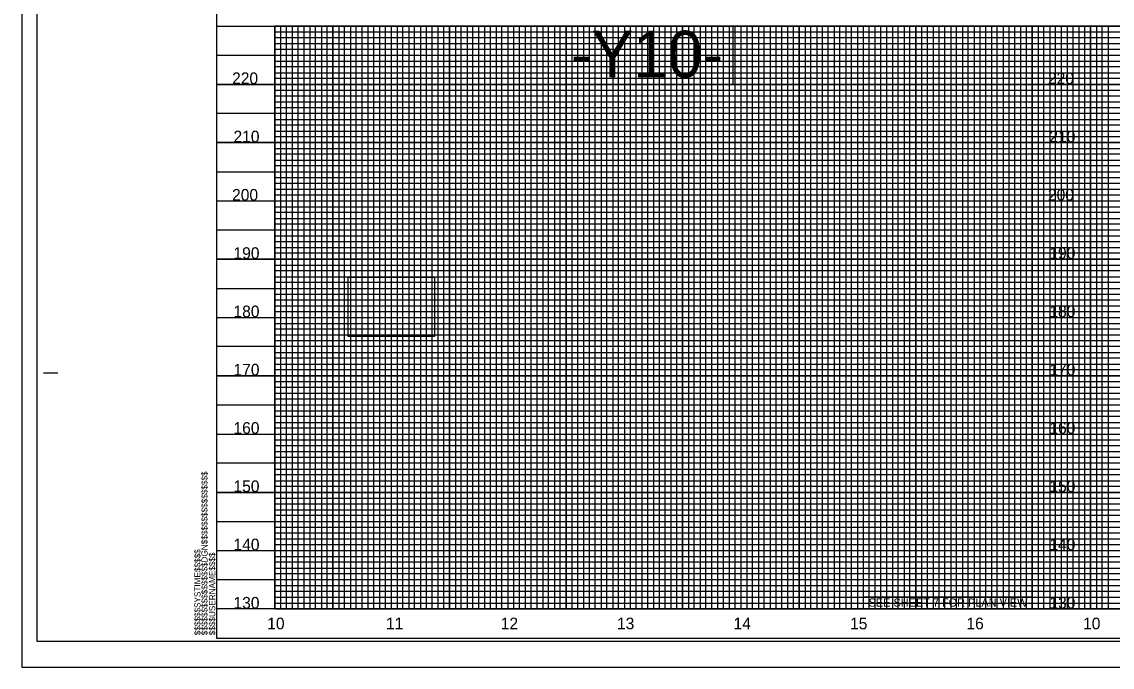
# Model space of a CAD drawing. Extents: x 1779926 to 1781626, y 618464 to 619564.
# Drawn here: x 1779926 to 1780862, y 618464 to 619018 of the extents above; entities that cross this region are included whole.
import ezdxf

# ---------------------------------------------------------------- set-up
doc = ezdxf.new("R2010")
doc.units = 0
for name, color, linetype in [('Exist Vertical Profile Horizontal Axis Label Major', 7, 'Continuous'), ('Exist Vertical Profile Vertical Axis Label', 7, 'Continuous'), ('Prop DSN Text', 7, 'Continuous'), ('Prop Grid Mask', 7, 'Continuous'), ('Sheet DOT Grid CELL', 7, 'Continuous'), ('Sheet Layout Profile Border Port 2', 7, 'Continuous'), ('Sheet Plot Border Inside CELL', 7, 'Continuous'), ('Sheet Plot Border Outside CELL', 7, 'Continuous'), ('Sheet Profile CELL', 7, 'Continuous'), ('Sheet Profile Grid Major CELL', 7, 'Continuous'), ('Sheet Profile Grid Middle CELL', 7, 'Continuous'), ('Sheet Profile Grid Minor CELL', 7, 'Continuous')]:
    doc.layers.add(name, color=color, linetype=linetype)

msp = doc.modelspace()

# ---------------------------------------------------------------- linework, layer by layer
at = {"layer": 'Prop Grid Mask'}
for points in [[(1780536.2, 619014.19), (1780392.96, 619014.19), (1780392.96, 618964.19), (1780536.2, 618964.19)], [(1780792.96, 619014.19), (1780842.96, 619014.19), (1780842.96, 618514.19), (1780792.96, 618514.19)], [(1780205.9, 618798.75), (1780280.15, 618798.75), (1780280.15, 618747.85), (1780205.9, 618747.85)], [(1780792.96, 618524.19), (1780647.96, 618524.19), (1780647.96, 618514.19), (1780792.96, 618514.19)]]:
    msp.add_lwpolyline(points, close=True, dxfattribs=at)
at = {"layer": 'Sheet DOT Grid CELL'}
for p, q in [((1780092.96, 619014.19), (1781592.85, 619014.19)), ((1780142.96, 619014.19), (1780142.96, 618514.19)), ((1780192.96, 619014.19), (1780192.96, 618514.19)), ((1780242.96, 619014.19), (1780242.96, 618514.19)), ((1780292.96, 619014.19), (1780292.96, 618514.19)), ((1780342.96, 619014.19), (1780342.96, 618514.19)), ((1780392.96, 619014.19), (1780392.96, 618514.19)), ((1780442.96, 619014.19), (1780442.96, 618514.19)), ((1780492.96, 619014.19), (1780492.96, 618514.19)), ((1780542.96, 619014.19), (1780542.96, 618514.19)), ((1780592.96, 619014.19), (1780592.96, 618514.19)), ((1780642.96, 619014.19), (1780642.96, 618514.19)), ((1780692.96, 619014.19), (1780692.96, 618514.19)), ((1780742.96, 619014.19), (1780742.96, 618514.19)), ((1780792.96, 619014.19), (1780792.96, 618514.19)), ((1780792.96, 618514.19), (1780792.96, 619014.19)), ((1780842.96, 619014.19), (1780842.96, 618514.19)), ((1780842.96, 618514.19), (1780842.96, 619014.19)), ((1780092.96, 618964.19), (1781592.85, 618964.19)), ((1780092.96, 618914.19), (1781592.85, 618914.19)), ((1780092.96, 618864.19), (1781592.85, 618864.19)), ((1780092.96, 618814.19), (1781592.85, 618814.19)), ((1780092.96, 618764.19), (1781592.85, 618764.19)), ((1780092.96, 618714.19), (1781592.85, 618714.19)), ((1780092.96, 618664.19), (1781592.85, 618664.19)), ((1780092.96, 618614.19), (1781592.85, 618614.19)), ((1780092.96, 618564.19), (1781592.85, 618564.19))]:
    msp.add_line(p, q, dxfattribs=at)
at = {"layer": 'Sheet Layout Profile Border Port 2'}
msp.add_lwpolyline([(1780142.96, 619014.19), (1781542.96, 619014.19), (1781542.96, 618514.19), (1780142.96, 618514.19)], close=True, dxfattribs=at)
msp.add_lwpolyline([(1781442.96, 619014.19), (1780142.96, 619014.19), (1780142.96, 618514.19), (1781542.96, 618514.19), (1781542.96, 619014.19)], dxfattribs=at)
at = {"layer": 'Sheet Plot Border Inside CELL'}
msp.add_lwpolyline([(1779938.96, 618486.64), (1781605.46, 618486.64), (1781605.46, 619541.74), (1779938.96, 619541.74)], close=True, dxfattribs=at)
at = {"layer": 'Sheet Plot Border Outside CELL'}
msp.add_lwpolyline([(1779925.96, 618464.19), (1781625.96, 618464.19), (1781625.96, 619564.19), (1779925.96, 619564.19)], close=True, dxfattribs=at)
at = {"layer": 'Sheet Profile CELL'}
for p, q in [((1780092.96, 619014.19), (1781592.96, 619014.19)), ((1779944.46, 618716.69), (1779956.96, 618716.69)), ((1781592.96, 618514.19), (1780092.96, 618514.19)), ((1780092.96, 618489.19), (1781592.96, 618489.19)), ((1780092.96, 618489.19), (1780092.96, 618489.19)), ((1780092.96, 618489.19), (1780092.96, 618489.19)), ((1780092.96, 618489.19), (1780092.96, 618489.19)), ((1780092.96, 618489.19), (1780092.96, 618489.19)), ((1780092.96, 618489.19), (1780092.96, 618489.19)), ((1780092.96, 618489.19), (1780092.96, 618489.19)), ((1780092.96, 618489.19), (1780092.96, 618489.19))]:
    msp.add_line(p, q, dxfattribs=at)
msp.add_lwpolyline([(1781592.96, 619539.19), (1780092.96, 619539.19), (1780092.96, 618489.19), (1781592.96, 618489.19)], close=True, dxfattribs=at)
msp.add_lwpolyline([(1780130.46, 618489.19), (1780130.46, 618489.19)], dxfattribs=at)
at = {"layer": 'Sheet Profile Grid Major CELL'}
for p, q in [((1780592.96, 619014.19), (1780642.96, 619014.19)), ((1780692.96, 619014.19), (1780742.96, 619014.19)), ((1780792.96, 619014.19), (1780842.96, 619014.19)), ((1780092.96, 618514.19), (1780092.96, 618514.19))]:
    msp.add_line(p, q, dxfattribs=at)
for points in [[(1780142.96, 619014.19), (1780142.96, 618514.19), (1780192.96, 618514.19), (1780192.96, 619014.19), (1780242.96, 619014.19), (1780242.96, 618514.19), (1780292.96, 618514.19), (1780292.96, 619014.19), (1780342.96, 619014.19), (1780342.96, 618514.19), (1780392.96, 618514.19), (1780392.96, 619014.19), (1780442.96, 619014.19), (1780442.96, 618514.19), (1780492.96, 618514.19), (1780492.96, 619014.19), (1780542.96, 619014.19), (1780542.96, 618514.19), (1780592.96, 618514.19), (1780592.96, 619014.19), (1780642.96, 619014.19), (1780642.96, 618514.19), (1780692.96, 618514.19), (1780692.96, 619014.19), (1780742.96, 619014.19), (1780742.96, 618514.19), (1780792.96, 618514.19), (1780792.96, 619014.19), (1780842.96, 619014.19), (1780842.96, 618514.19), (1780892.96, 618514.19)], [(1781592.96, 618964.19), (1780092.96, 618964.19)], [(1781592.96, 618914.19), (1780092.96, 618914.19), (1780092.96, 618864.19), (1781592.96, 618864.19)], [(1781592.96, 618814.19), (1780092.96, 618814.19), (1780092.96, 618764.19), (1781592.96, 618764.19)], [(1781592.96, 618714.19), (1780092.96, 618714.19), (1780092.96, 618664.19), (1781592.96, 618664.19)], [(1781592.96, 618614.19), (1780092.96, 618614.19), (1780092.96, 618614.19), (1780092.96, 618564.19), (1781592.96, 618564.19)], [(1781592.96, 618514.19), (1780092.96, 618514.19)]]:
    msp.add_lwpolyline(points, dxfattribs=at)
at = {"layer": 'Sheet Profile Grid Middle CELL'}
for points in [[(1780117.96, 619014.19), (1780167.96, 619014.19), (1780167.96, 618514.19), (1780217.96, 618514.19), (1780217.96, 619014.19), (1780267.96, 619014.19), (1780267.96, 618514.19), (1780317.96, 618514.19), (1780317.96, 619014.19), (1780367.96, 619014.19), (1780367.96, 618514.19), (1780417.96, 618514.19), (1780417.96, 619014.19), (1780467.96, 619014.19), (1780467.96, 618514.19), (1780517.96, 618514.19), (1780517.96, 619014.19), (1780567.96, 619014.19), (1780567.96, 618514.19), (1780617.96, 618514.19), (1780617.96, 619014.19), (1780667.96, 619014.19), (1780667.96, 618514.19), (1780717.96, 618514.19), (1780717.96, 618514.19), (1780717.96, 619014.19), (1780767.96, 619014.19), (1780767.96, 618514.19), (1780817.96, 618514.19), (1780817.96, 619014.19), (1780867.96, 619014.19)], [(1780092.96, 618989.19), (1781592.96, 618989.19)], [(1781592.96, 618939.19), (1780092.96, 618939.19), (1780092.96, 618889.19), (1781592.96, 618889.19)], [(1781592.96, 618839.19), (1780092.96, 618839.19), (1780092.96, 618789.19), (1781592.96, 618789.19)], [(1781592.96, 618739.19), (1780092.96, 618739.19), (1780092.96, 618689.19), (1781592.96, 618689.19)], [(1781592.96, 618639.19), (1780092.96, 618639.19), (1780092.96, 618589.19), (1781592.96, 618589.19)], [(1781592.96, 618539.19), (1780092.96, 618539.19)]]:
    msp.add_lwpolyline(points, dxfattribs=at)
at = {"layer": 'Sheet Profile Grid Minor CELL'}
for p, q in [((1780142.96, 619009.19), (1781542.96, 619009.19)), ((1781542.96, 619004.19), (1780142.96, 619004.19)), ((1780142.96, 618999.19), (1781542.96, 618999.19)), ((1781542.96, 618994.19), (1780142.96, 618994.19)), ((1780142.96, 618984.19), (1781542.96, 618984.19)), ((1781542.96, 618979.19), (1780142.96, 618979.19)), ((1780142.96, 618974.19), (1781542.96, 618974.19)), ((1781542.96, 618969.19), (1780142.96, 618969.19)), ((1780142.96, 618959.19), (1781542.96, 618959.19)), ((1781542.96, 618954.19), (1780142.96, 618954.19)), ((1780142.96, 618949.19), (1781542.96, 618949.19)), ((1781542.96, 618944.19), (1780142.96, 618944.19)), ((1780142.96, 618934.19), (1781542.96, 618934.19)), ((1781542.96, 618929.19), (1780142.96, 618929.19)), ((1780142.96, 618924.19), (1781542.96, 618924.19)), ((1781542.96, 618919.19), (1780142.96, 618919.19)), ((1780142.96, 618909.19), (1781542.96, 618909.19)), ((1781542.96, 618904.19), (1780142.96, 618904.19)), ((1780142.96, 618899.19), (1781542.96, 618899.19)), ((1781542.96, 618894.19), (1780142.96, 618894.19)), ((1780142.96, 618884.19), (1781542.96, 618884.19)), ((1781542.96, 618879.19), (1780142.96, 618879.19)), ((1780142.96, 618874.19), (1781542.96, 618874.19)), ((1781542.96, 618869.19), (1780142.96, 618869.19)), ((1780142.96, 618859.19), (1781542.96, 618859.19)), ((1781542.96, 618854.19), (1780142.96, 618854.19)), ((1780142.96, 618849.19), (1781542.96, 618849.19)), ((1781542.96, 618844.19), (1780142.96, 618844.19)), ((1780142.96, 618834.19), (1781542.96, 618834.19)), ((1781542.96, 618829.19), (1780142.96, 618829.19)), ((1780142.96, 618824.19), (1781542.96, 618824.19)), ((1781542.96, 618819.19), (1780142.96, 618819.34)), ((1780142.96, 618809.19), (1781542.96, 618809.19)), ((1781542.96, 618804.19), (1780142.96, 618804.19)), ((1780142.96, 618799.19), (1781542.96, 618799.19)), ((1781542.96, 618794.19), (1780142.96, 618794.19)), ((1780142.96, 618784.19), (1781542.96, 618784.19)), ((1781542.96, 618779.19), (1780142.96, 618779.19)), ((1780142.96, 618774.19), (1781542.96, 618774.19)), ((1781542.96, 618769.19), (1780142.96, 618769.19)), ((1780142.96, 618759.19), (1781542.96, 618759.19)), ((1781542.96, 618754.19), (1780142.96, 618754.19)), ((1780142.96, 618749.19), (1781542.96, 618749.19)), ((1781542.96, 618744.19), (1780142.96, 618744.19)), ((1780142.96, 618734.19), (1781542.96, 618734.19)), ((1781542.96, 618729.19), (1780142.96, 618729.19)), ((1780142.96, 618724.19), (1781542.96, 618724.19)), ((1781542.96, 618719.19), (1780142.96, 618719.19)), ((1780142.96, 618709.19), (1781542.96, 618709.19)), ((1781542.96, 618704.19), (1780142.96, 618704.19)), ((1780142.96, 618699.19), (1781542.96, 618699.19)), ((1781542.96, 618694.19), (1780142.96, 618694.19)), ((1780142.96, 618684.19), (1781542.96, 618684.19)), ((1781542.96, 618679.19), (1780142.96, 618679.19)), ((1780142.96, 618674.19), (1781542.96, 618674.19)), ((1781542.96, 618669.19), (1780142.96, 618669.19)), ((1780142.96, 618659.19), (1781542.96, 618659.19)), ((1781542.96, 618654.19), (1780142.96, 618654.19)), ((1780142.96, 618649.19), (1781542.96, 618649.19)), ((1781542.96, 618644.19), (1780142.96, 618644.19)), ((1780142.96, 618634.19), (1781542.96, 618634.19)), ((1781542.96, 618629.19), (1780142.96, 618629.19)), ((1780142.96, 618624.19), (1781542.96, 618624.19)), ((1781542.96, 618619.19), (1780142.96, 618619.19)), ((1780142.96, 618609.19), (1781542.96, 618609.19)), ((1781542.96, 618604.19), (1780142.96, 618604.19)), ((1780142.96, 618599.19), (1781542.96, 618599.19)), ((1781542.96, 618594.19), (1780142.96, 618594.19)), ((1780142.96, 618584.19), (1781542.96, 618584.19)), ((1781542.96, 618579.19), (1780142.96, 618579.19)), ((1780142.96, 618574.19), (1781542.96, 618574.19)), ((1781542.96, 618569.19), (1780142.96, 618569.19)), ((1780142.96, 618559.19), (1781542.96, 618559.19)), ((1781542.96, 618554.19), (1780142.96, 618554.19)), ((1780142.96, 618549.19), (1781542.96, 618549.19)), ((1781542.96, 618544.19), (1780142.96, 618544.19)), ((1780142.96, 618534.19), (1781542.96, 618534.19)), ((1781542.96, 618529.19), (1780142.96, 618529.19)), ((1780142.96, 618524.19), (1781542.96, 618524.19)), ((1780142.96, 618519.19), (1781542.96, 618519.19))]:
    msp.add_line(p, q, dxfattribs=at)
for points in [[(1780142.96, 619014.19), (1780147.96, 619014.19), (1780147.96, 618514.19), (1780152.96, 618514.19), (1780152.96, 619014.19), (1780157.96, 619014.19), (1780157.96, 618514.19), (1780162.96, 618514.19), (1780162.96, 619014.19), (1780172.96, 619014.19), (1780172.96, 618514.19), (1780177.96, 618514.19), (1780177.96, 619014.19), (1780182.96, 619014.19), (1780182.96, 618514.19), (1780187.96, 618514.19), (1780197.96, 618514.19), (1780202.96, 618514.19), (1780202.96, 619014.19), (1780207.96, 619014.19), (1780207.96, 618514.19), (1780212.96, 618514.19), (1780212.96, 619014.19), (1780222.96, 619014.19), (1780222.96, 618514.19), (1780227.96, 618514.19), (1780227.96, 619014.19), (1780232.96, 619014.19), (1780232.96, 618514.19), (1780237.96, 618514.19), (1780237.96, 619014.19), (1780247.96, 619014.19), (1780247.96, 618514.19), (1780252.96, 618514.19), (1780252.96, 619014.19), (1780257.96, 619014.19), (1780257.96, 618514.19), (1780262.96, 618514.19), (1780262.96, 619014.19), (1780272.96, 619014.19), (1780272.96, 618514.19), (1780277.96, 618514.19), (1780277.96, 619014.19), (1780282.96, 619014.19), (1780282.96, 618514.19), (1780287.96, 618514.19), (1780287.96, 619014.19), (1780297.96, 619014.19), (1780297.96, 618514.19), (1780302.96, 618514.19), (1780302.96, 619014.19), (1780307.96, 619014.19), (1780307.96, 618514.19), (1780312.96, 618514.19), (1780312.96, 619014.19), (1780322.96, 619014.19), (1780322.96, 618514.19), (1780327.96, 618514.19), (1780327.96, 619014.19), (1780332.96, 619014.19), (1780332.96, 618514.19), (1780337.96, 618514.19), (1780337.96, 619014.19), (1780347.96, 619014.19), (1780347.96, 618514.19), (1780352.96, 618514.19), (1780352.96, 619014.19), (1780357.96, 619014.19), (1780357.96, 618514.19)], [(1780187.96, 618514.19), (1780187.96, 619014.19), (1780197.96, 619014.19), (1780197.96, 618514.19)], [(1780357.96, 618514.19), (1780362.96, 618514.19), (1780362.96, 619014.19), (1780372.96, 619014.19), (1780372.96, 618514.19), (1780377.96, 618514.19), (1780377.96, 619014.19), (1780382.96, 619014.19), (1780382.96, 618514.19), (1780387.96, 618514.19), (1780387.96, 619014.19), (1780397.96, 619014.19), (1780397.96, 618514.19), (1780402.96, 618514.19), (1780402.96, 619014.19), (1780407.96, 619014.19), (1780407.96, 618514.19), (1780412.96, 618514.19), (1780412.96, 619014.19), (1780422.96, 619014.19), (1780422.96, 618514.19), (1780427.96, 618514.19), (1780427.96, 619014.19), (1780432.96, 619014.19), (1780432.96, 618514.19), (1780437.96, 618514.19), (1780437.96, 619014.19), (1780447.96, 619014.19), (1780447.96, 618514.19), (1780452.96, 618514.19), (1780452.96, 619014.19), (1780457.96, 619014.19), (1780457.96, 618514.19), (1780462.96, 618514.19), (1780462.96, 619014.19), (1780472.96, 619014.19), (1780472.96, 618514.19), (1780477.96, 618514.19), (1780477.96, 619014.19), (1780482.96, 619014.19), (1780482.96, 618514.19), (1780487.96, 618514.19), (1780487.96, 619014.19), (1780497.96, 619014.19), (1780497.96, 618514.19), (1780502.96, 618514.19), (1780502.96, 619014.19), (1780507.96, 619014.19), (1780507.96, 618514.19), (1780512.96, 618514.19), (1780512.96, 619014.19), (1780522.96, 619014.19), (1780522.96, 618514.19), (1780527.96, 618514.19), (1780527.96, 619014.19), (1780532.96, 619014.19), (1780532.96, 618514.19), (1780537.96, 618514.19), (1780537.96, 619014.19), (1780547.96, 619014.19), (1780547.96, 618514.19), (1780552.96, 618514.19), (1780552.96, 619014.19), (1780557.96, 619014.19), (1780557.96, 618514.19), (1780562.96, 618514.19), (1780562.96, 619014.19), (1780572.96, 619014.19), (1780572.96, 618514.19), (1780577.96, 618514.19), (1780577.96, 619014.19), (1780582.96, 619014.19), (1780582.96, 618514.19), (1780587.96, 618514.19), (1780587.96, 619014.19), (1780597.96, 619014.19), (1780597.96, 618514.19), (1780602.96, 618514.19), (1780602.96, 619014.19), (1780607.96, 619014.19), (1780607.96, 618514.19), (1780612.96, 618514.19), (1780612.96, 619014.19), (1780622.96, 619014.19), (1780622.96, 618514.19), (1780627.96, 618514.19), (1780627.96, 619014.19), (1780632.96, 619014.19), (1780632.96, 618514.19), (1780637.96, 618514.19), (1780637.96, 619014.19), (1780647.96, 619014.19), (1780647.96, 618514.19), (1780652.96, 618514.19), (1780652.96, 619014.19), (1780657.96, 619014.19), (1780657.96, 618514.19), (1780662.96, 618514.19), (1780662.96, 619014.19), (1780672.96, 619014.19)], [(1780672.96, 619014.19), (1780672.96, 618514.19), (1780677.96, 618514.19), (1780677.96, 619014.19), (1780682.96, 619014.19), (1780682.96, 618514.19), (1780687.96, 618514.19), (1780687.96, 619014.19), (1780697.96, 619014.19), (1780697.96, 618514.19), (1780702.96, 618514.19), (1780702.96, 619014.19), (1780707.96, 619014.19), (1780707.96, 618514.19), (1780712.96, 618514.19), (1780712.96, 619014.19), (1780722.96, 619014.19), (1780722.96, 618514.19), (1780727.96, 618514.19), (1780727.96, 619014.19), (1780732.96, 619014.19), (1780732.96, 618514.19), (1780737.96, 618514.19), (1780737.96, 619014.19), (1780747.96, 619014.19), (1780747.96, 618514.19), (1780752.96, 618514.19), (1780752.96, 619014.19), (1780757.96, 619014.19), (1780757.96, 618514.19), (1780762.96, 618514.19), (1780762.96, 619014.19), (1780772.96, 619014.19), (1780772.96, 618514.19), (1780777.96, 618514.19), (1780777.96, 619014.19), (1780782.96, 619014.19), (1780782.96, 618514.19), (1780787.96, 618514.19), (1780787.96, 619014.19), (1780797.96, 619014.19), (1780797.96, 618514.19), (1780797.96, 618514.19), (1780802.96, 618514.19), (1780802.96, 619014.19), (1780807.96, 619014.19), (1780807.96, 618514.19), (1780812.96, 618514.19), (1780812.96, 619014.19), (1780822.96, 619014.19), (1780822.96, 618514.19), (1780827.96, 618514.19), (1780827.96, 619014.19), (1780832.96, 619014.19), (1780832.96, 618514.19), (1780837.96, 618514.19), (1780837.96, 619014.19), (1780847.96, 619014.19), (1780847.96, 618514.19), (1780852.96, 618514.19), (1780852.96, 619014.19), (1780857.96, 619014.19), (1780857.96, 618514.19), (1780862.96, 618514.19)]]:
    msp.add_lwpolyline(points, dxfattribs=at)

# ---------------------------------------------------------------- texts
at = {"layer": 'Exist Vertical Profile Horizontal Axis Label Major'}
for s, p in [('10', (1780136.54, 618496.69)), ('12', (1780336.93, 618496.69)), ('13', (1780436.61, 618496.69)), ('16', (1780736.42, 618496.69)), ('10', (1780836.54, 618496.69)), ('11', (1780238.38, 618496.69)), ('14', (1780536.66, 618496.69)), ('15', (1780636.59, 618496.69))]:
    msp.add_text(s, height=10, dxfattribs=at).set_placement(p)
at = {"layer": 'Exist Vertical Profile Vertical Axis Label'}
for s, p in [('220', (1780106.39, 618964.44)), ('220', (1780806.39, 618964.44)), ('210', (1780107.59, 618914.44)), ('210', (1780807.59, 618914.44)), ('200', (1780106.39, 618864.44)), ('200', (1780806.39, 618864.44)), ('190', (1780107.59, 618814.44)), ('190', (1780807.59, 618814.44)), ('180', (1780107.59, 618764.44)), ('180', (1780807.59, 618764.44)), ('170', (1780107.59, 618714.44)), ('170', (1780807.59, 618714.44)), ('160', (1780107.59, 618664.44)), ('160', (1780807.59, 618664.44)), ('150', (1780107.59, 618614.44)), ('150', (1780807.59, 618614.44)), ('140', (1780107.59, 618564.44)), ('140', (1780807.59, 618564.44)), ('130', (1780107.59, 618514.44)), ('130', (1780807.59, 618514.44))]:
    msp.add_text(s, height=10, dxfattribs=at).set_placement(p)
at = {"layer": 'Prop DSN Text'}
for s, height, p in [('-Y10-', 40, (1780397.01, 618970.14)), ('SEE SHEET 7 FOR PLAN VIEW', 7, (1780652.54, 618516.14))]:
    msp.add_text(s, height=height, dxfattribs=at).set_placement(p)
at = {"layer": 'Sheet Profile CELL'}
for s, p in [('$$$$$$$$$$$$$$$$DGN$$$$$$$$$$$$$$$$', (1780085.32, 618491.57)), ('$$$$$$SYSTIME$$$$$', (1780079.27, 618491.57)), ('$$$$USERNAME$$$$', (1780091.9, 618491.58))]:
    msp.add_text(s, height=5.25, rotation=90, dxfattribs=at).set_placement(p)

doc.saveas('drawing.dxf')
